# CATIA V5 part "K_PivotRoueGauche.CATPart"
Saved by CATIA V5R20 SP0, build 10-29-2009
Part number: pivot_roue_gauche
Publications: "Corps principal", "largeur pivot", "Point.1", "Droite.1", "Point.2", "Droite.3"
Bounding box of the stored display mesh (mm): x -20 to 20, y 500 to 625, z 0 to 0
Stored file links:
  G:\Khaled_CFAO_2011\ST2M\ST2M_GR1\cdurantin\cdurantin\Khaled\CAD_ThinkMOTION\K_PivotRoueGauche.CATPart
  G:\Khaled_CFAO_2011\ST2M\ST2M_GR1\cdurantin\cdurantin\Khaled\CAD_ThinkMOTION\K_Corps.CATPart
  G:\Khaled_CFAO_2011\ST2M\ST2M_GR1\cdurantin\cdurantin\Khaled\CAD_ThinkMOTION\K_Part4.CATPart
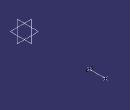
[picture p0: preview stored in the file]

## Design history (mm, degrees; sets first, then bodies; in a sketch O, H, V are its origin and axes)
Parameters
  `largeur pivot` = 125 mm
External parameters (linked from other documents)
  `External.Longueur de barres du corps` = 800 mm
  `External.largeur de la glissière` = 100 mm
Body1 (main body)
  Point1: type OnPlane, Support xy-plane, H 0, V 500 {= `External.Longueur de barres du corps` /2+`External.largeur de la glissière`}, Direction (1, 0, 0)
  Line1: type PtDir, RefPoint Point1, Direction yz-plane, Start -20, End 20
  Point2: type OnPlane, Support xy-plane, H 0, V 625 {= `External.Longueur de barres du corps` /2+`External.largeur de la glissière` +`largeur pivot`}, Direction (1, 0, 0)
  Line2: type PtPt, FirstPoint Point1, SecondPoint Point2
